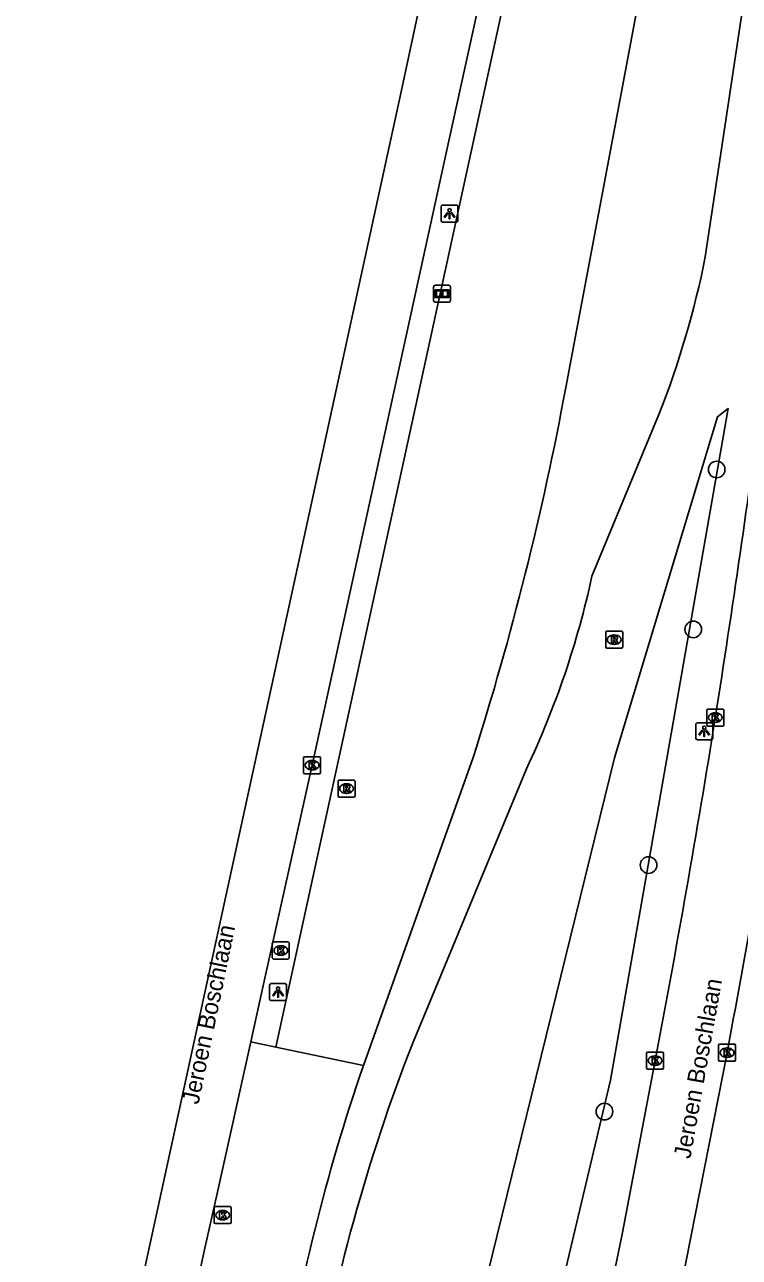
# Model space of a CAD drawing. Extents: x 163010 to 163853, y 382793 to 383982.
# Drawn here: x 163134.3 to 163176.4, y 382934.2 to 383006.7 of the extents above; entities that cross this region are included whole.
import ezdxf

# ---------------------------------------------------------------- set-up
doc = ezdxf.new("R2010")
doc.units = 0
for name, color, linetype in [('IMGEO_Berm_groen', 7, 'Continuous'), ('IMGEO_Boom', 7, 'Continuous'), ('IMGEO_Informatiebord', 7, 'Continuous'), ('IMGEO_Kolk', 7, 'Continuous'), ('IMGEO_Lichtpunt', 7, 'Continuous'), ('IMGEO_Openbare_ruimte_label', 7, 'Continuous'), ('IMGEO_Rijbaan_lokaal_gesloten', 7, 'Continuous'), ('IMGEO_Rijbaan_regionaal_gesloten', 7, 'Continuous'), ('IMGEO_Rioolput', 7, 'Continuous')]:
    doc.layers.add(name, color=color, linetype=linetype)

msp = doc.modelspace()

# ---------------------------------------------------------------- linework, layer by layer
at = {"layer": 'IMGEO_Berm_groen'}
for points in [[(163167.335, 383030.022), (163149.123, 382946.557)], [(163174.387, 382993.005), (163175.441, 383000), (163179.814, 383029.04)], [(163173.756, 383028.282), (163172.571, 383019.306), (163168.939, 383000), (163166.178, 382985.326)], [(163160.593, 382909.986), (163168.816, 382944.6), (163175.739, 382984.091), (163175.109, 382983.61), (163169.045, 382963.559), (163155.533, 382908.637)], [(163167.716, 382974.235), (163171.658, 382983.735)], [(163160.728, 382963.579), (163154.271, 382945.466)], [(163157.194, 382946.851), (163163.863, 382962.916)], [(163147.641, 382946.871), (163149.123, 382946.557)], [(163149.123, 382946.557), (163154.271, 382945.466)]]:
    msp.add_lwpolyline(points, dxfattribs=at)
for centre, radius, start, end in [((163120.584, 383003.807), 54.876, 338.54483, 348.64731), ((162989.182, 383018.126), 180.009, 342.36061, 349.5012), ((163116.601, 382985.319), 52.303, 334.63795, 347.76479), ((163256.409, 382908.014), 106.546, 158.62275, 170.52914), ((163259.849, 382908.974), 111.707, 160.93273, 171.28168)]:
    msp.add_arc(centre, radius, start, end, dxfattribs=at)
at = {"layer": 'IMGEO_Boom'}
for centre in [(163175.056, 382980.509), (163173.679, 382971.111), (163171.048, 382957.253), (163168.454, 382942.76)]:
    msp.add_circle(centre, 0.489, dxfattribs=at)
at = {"layer": 'IMGEO_Informatiebord'}
for p, q in [((163158.402, 382990.443), (163158.402, 382991.243)), ((163158.402, 382991.243), (163158.402, 382990.443)), ((163158.502, 382991.343), (163159.292, 382991.343)), ((163159.292, 382991.343), (163158.502, 382991.343)), ((163159.392, 382991.243), (163159.392, 382990.443)), ((163159.392, 382990.443), (163159.392, 382991.243)), ((163159.292, 382990.343), (163158.502, 382990.343)), ((163158.502, 382990.343), (163159.292, 382990.343))]:
    msp.add_line(p, q, dxfattribs=at)
for points in [[(163158.503, 382991.075), (163159.291, 382991.075), (163159.291, 382990.611), (163158.503, 382990.611), (163158.503, 382991.075)], [(163158.568, 382991.01), (163158.568, 382990.676), (163158.843, 382990.676), (163158.844, 382990.889), (163158.948, 382990.89), (163158.949, 382990.676), (163159.226, 382990.676), (163159.226, 382991.01), (163158.95, 382991.01), (163158.95, 382990.93), (163158.844, 382990.93), (163158.844, 382991.01), (163158.568, 382991.01)]]:
    msp.add_lwpolyline(points, dxfattribs=at)
for centre, start, end in [((163158.502, 382991.243), 90, 180), ((163158.502, 382991.243), 90, 180), ((163159.292, 382991.243), 0, 90), ((163159.292, 382991.243), 360, 90), ((163158.502, 382990.443), 180, 270), ((163158.502, 382990.443), 180, 270), ((163159.292, 382990.443), 270, 0), ((163159.292, 382990.443), 270, 0)]:
    msp.add_arc(centre, 0.1, start, end, dxfattribs=at)
at = {"layer": 'IMGEO_Kolk'}
for p, q in [((163174.474, 382965.499), (163174.474, 382966.351)), ((163174.549, 382966.425), (163175.401, 382966.425)), ((163174.962, 382966.205), (163174.987, 382966.205)), ((163175.475, 382966.351), (163175.475, 382965.499)), ((163175.401, 382965.425), (163174.549, 382965.425)), ((163174.985, 382965.645), (163174.96, 382965.645)), ((163150.753, 382962.698), (163150.753, 382963.55)), ((163150.828, 382963.624), (163151.68, 382963.624)), ((163151.241, 382963.404), (163151.266, 382963.404)), ((163151.754, 382963.55), (163151.754, 382962.698)), ((163151.68, 382962.624), (163150.828, 382962.624)), ((163151.264, 382962.844), (163151.239, 382962.844)), ((163148.913, 382951.806), (163148.913, 382952.658)), ((163148.988, 382952.732), (163149.84, 382952.732)), ((163149.401, 382952.512), (163149.426, 382952.512)), ((163149.914, 382952.658), (163149.914, 382951.806)), ((163149.84, 382951.732), (163148.988, 382951.732)), ((163149.424, 382951.952), (163149.399, 382951.952)), ((163175.168, 382945.798), (163175.168, 382946.65)), ((163175.243, 382946.724), (163176.095, 382946.724)), ((163175.656, 382946.504), (163175.681, 382946.504)), ((163176.169, 382946.65), (163176.169, 382945.798)), ((163170.93, 382945.331), (163170.93, 382946.183)), ((163171.005, 382946.257), (163171.857, 382946.257)), ((163171.418, 382946.037), (163171.443, 382946.037)), ((163171.931, 382946.183), (163171.931, 382945.331)), ((163176.095, 382945.724), (163175.243, 382945.724)), ((163175.679, 382945.944), (163175.654, 382945.944)), ((163171.857, 382945.257), (163171.005, 382945.257)), ((163171.441, 382945.477), (163171.416, 382945.477)), ((163145.494, 382936.248), (163145.494, 382937.1)), ((163145.569, 382937.174), (163146.421, 382937.174)), ((163145.982, 382936.954), (163146.007, 382936.954)), ((163146.495, 382937.1), (163146.495, 382936.248)), ((163146.421, 382936.174), (163145.569, 382936.174)), ((163146.005, 382936.394), (163145.98, 382936.394))]:
    msp.add_line(p, q, dxfattribs=at)
for points in [[(163174.474, 382965.499), (163174.474, 382966.351)], [(163174.549, 382966.425), (163175.401, 382966.425)], [(163174.795, 382966.125), (163174.918, 382966.125), (163174.918, 382965.974), (163175.048, 382966.125), (163175.212, 382966.125), (163175.066, 382965.974), (163175.219, 382965.725), (163175.067, 382965.725), (163174.982, 382965.889), (163174.918, 382965.822), (163174.918, 382965.725), (163174.795, 382965.725), (163174.795, 382966.125)], [(163175.475, 382966.351), (163175.475, 382965.499)], [(163175.401, 382965.425), (163174.549, 382965.425)], [(163150.753, 382962.698), (163150.753, 382963.55)], [(163150.828, 382963.624), (163151.68, 382963.624)], [(163151.074, 382963.324), (163151.197, 382963.324), (163151.197, 382963.173), (163151.327, 382963.324), (163151.491, 382963.324), (163151.345, 382963.173), (163151.498, 382962.924), (163151.346, 382962.924), (163151.261, 382963.088), (163151.197, 382963.021), (163151.197, 382962.924), (163151.074, 382962.924), (163151.074, 382963.324)], [(163151.754, 382963.55), (163151.754, 382962.698)], [(163151.68, 382962.624), (163150.828, 382962.624)], [(163148.913, 382951.806), (163148.913, 382952.658)], [(163148.988, 382952.732), (163149.84, 382952.732)], [(163149.234, 382952.432), (163149.357, 382952.432), (163149.357, 382952.281), (163149.487, 382952.432), (163149.651, 382952.432), (163149.505, 382952.281), (163149.658, 382952.032), (163149.506, 382952.032), (163149.421, 382952.196), (163149.357, 382952.129), (163149.357, 382952.032), (163149.234, 382952.032), (163149.234, 382952.432)], [(163149.914, 382952.658), (163149.914, 382951.806)], [(163149.84, 382951.732), (163148.988, 382951.732)], [(163175.168, 382945.798), (163175.168, 382946.65)], [(163175.243, 382946.724), (163176.095, 382946.724)], [(163175.489, 382946.424), (163175.612, 382946.424), (163175.612, 382946.273), (163175.742, 382946.424), (163175.906, 382946.424), (163175.76, 382946.273), (163175.913, 382946.024), (163175.761, 382946.024), (163175.676, 382946.188), (163175.612, 382946.121), (163175.612, 382946.024), (163175.489, 382946.024), (163175.489, 382946.424)], [(163176.169, 382946.65), (163176.169, 382945.798)], [(163170.93, 382945.331), (163170.93, 382946.183)], [(163171.005, 382946.257), (163171.857, 382946.257)], [(163171.251, 382945.957), (163171.374, 382945.957), (163171.374, 382945.806), (163171.504, 382945.957), (163171.668, 382945.957), (163171.522, 382945.806), (163171.675, 382945.557), (163171.523, 382945.557), (163171.438, 382945.721), (163171.374, 382945.654), (163171.374, 382945.557), (163171.251, 382945.557), (163171.251, 382945.957)], [(163171.931, 382946.183), (163171.931, 382945.331)], [(163176.095, 382945.724), (163175.243, 382945.724)], [(163171.857, 382945.257), (163171.005, 382945.257)], [(163145.494, 382936.248), (163145.494, 382937.1)], [(163145.569, 382937.174), (163146.421, 382937.174)], [(163146.495, 382937.1), (163146.495, 382936.248)], [(163146.421, 382936.174), (163145.569, 382936.174)], [(163145.815, 382936.874), (163145.938, 382936.874), (163145.938, 382936.723), (163146.068, 382936.874), (163146.232, 382936.874), (163146.086, 382936.723), (163146.239, 382936.474), (163146.087, 382936.474), (163146.002, 382936.638), (163145.938, 382936.571), (163145.938, 382936.474), (163145.815, 382936.474), (163145.815, 382936.874)]]:
    msp.add_lwpolyline(points, dxfattribs=at)
for centre, start, end in [((163174.551, 382966.349), 91.55205, 178.44795), ((163174.551, 382966.349), 91.55205, 178.44795), ((163175.399, 382966.349), 1.55205, 88.44795), ((163175.399, 382966.349), 1.55205, 88.44795), ((163174.551, 382965.501), 181.55205, 268.44795), ((163174.551, 382965.501), 181.55205, 268.44795), ((163175.399, 382965.501), 271.55205, 358.44795), ((163175.399, 382965.501), 271.55205, 358.44795), ((163150.83, 382963.548), 91.55205, 178.44795), ((163150.83, 382963.548), 91.55205, 178.44795), ((163151.678, 382963.548), 1.55205, 88.44795), ((163151.678, 382963.548), 1.55205, 88.44795), ((163150.83, 382962.7), 181.55205, 268.44795), ((163150.83, 382962.7), 181.55205, 268.44795), ((163151.678, 382962.7), 271.55205, 358.44795), ((163151.678, 382962.7), 271.55205, 358.44795), ((163148.99, 382952.656), 91.55205, 178.44795), ((163148.99, 382952.656), 91.55205, 178.44795), ((163149.838, 382952.656), 1.55205, 88.44795), ((163149.838, 382952.656), 1.55205, 88.44795), ((163148.99, 382951.808), 181.55205, 268.44795), ((163148.99, 382951.808), 181.55205, 268.44795), ((163149.838, 382951.808), 271.55205, 358.44795), ((163149.838, 382951.808), 271.55205, 358.44795), ((163175.245, 382946.648), 91.55205, 178.44795), ((163175.245, 382946.648), 91.55205, 178.44795), ((163176.093, 382946.648), 1.55205, 88.44795), ((163176.093, 382946.648), 1.55205, 88.44795), ((163171.007, 382946.181), 91.55205, 178.44795), ((163171.007, 382946.181), 91.55205, 178.44795), ((163171.855, 382946.181), 1.55205, 88.44795), ((163171.855, 382946.181), 1.55205, 88.44795), ((163175.245, 382945.8), 181.55205, 268.44795), ((163175.245, 382945.8), 181.55205, 268.44795), ((163176.093, 382945.8), 271.55205, 358.44795), ((163176.093, 382945.8), 271.55205, 358.44795), ((163171.007, 382945.333), 181.55205, 268.44795), ((163171.007, 382945.333), 181.55205, 268.44795), ((163171.855, 382945.333), 271.55205, 358.44795), ((163171.855, 382945.333), 271.55205, 358.44795), ((163145.571, 382937.098), 91.55205, 178.44795), ((163145.571, 382937.098), 91.55205, 178.44795), ((163146.419, 382937.098), 1.55205, 88.44795), ((163146.419, 382937.098), 1.55205, 88.44795), ((163145.571, 382936.25), 181.55205, 268.44795), ((163145.571, 382936.25), 181.55205, 268.44795), ((163146.419, 382936.25), 271.55205, 358.44795), ((163146.419, 382936.25), 271.55205, 358.44795)]:
    msp.add_arc(centre, 0.0765, start, end, dxfattribs=at)
for centre, major_axis, ratio, start_param, end_param in [((163174.961, 382965.925), (-0.387, 0.002), 0.722429, 4.712389, 7.853982), ((163174.986, 382965.925), (-0.39, 0.002), 0.717154, 1.570796, 4.712389), ((163151.24, 382963.124), (-0.387, 0.002), 0.722429, 4.712389, 7.853982), ((163151.265, 382963.124), (-0.39, 0.002), 0.717154, 1.570796, 4.712389), ((163149.4, 382952.232), (-0.387, 0.002), 0.722429, 4.712389, 7.853982), ((163149.425, 382952.232), (-0.39, 0.002), 0.717154, 1.570796, 4.712389), ((163175.655, 382946.224), (-0.387, 0.002), 0.722429, 4.712389, 7.853982), ((163175.68, 382946.224), (-0.39, 0.002), 0.717154, 1.570796, 4.712389), ((163171.417, 382945.757), (-0.387, 0.002), 0.722429, 4.712389, 7.853982), ((163171.442, 382945.757), (-0.39, 0.002), 0.717154, 1.570796, 4.712389), ((163145.981, 382936.674), (-0.387, 0.002), 0.722429, 4.712389, 7.853982), ((163146.006, 382936.674), (-0.39, 0.002), 0.717154, 1.570796, 4.712389)]:
    msp.add_ellipse(centre, major_axis=major_axis, ratio=ratio, start_param=start_param, end_param=end_param, dxfattribs=at)
at = {"layer": 'IMGEO_Lichtpunt'}
for p, q in [((163158.84, 382995.954), (163158.84, 382995.147)), ((163158.84, 382995.954), (163158.84, 382995.147)), ((163159.742, 382996.049), (163158.934, 382996.049)), ((163159.742, 382996.049), (163158.934, 382996.049)), ((163159.836, 382995.147), (163159.836, 382995.954)), ((163159.836, 382995.147), (163159.836, 382995.954)), ((163158.934, 382995.053), (163159.742, 382995.053)), ((163158.934, 382995.053), (163159.742, 382995.053)), ((163173.824, 382965.526), (163173.824, 382964.719)), ((163173.824, 382965.526), (163173.824, 382964.719)), ((163174.726, 382965.621), (163173.918, 382965.621)), ((163174.726, 382965.621), (163173.918, 382965.621)), ((163174.82, 382964.719), (163174.82, 382965.526)), ((163174.82, 382964.719), (163174.82, 382965.526)), ((163173.918, 382964.625), (163174.726, 382964.625)), ((163173.918, 382964.625), (163174.726, 382964.625)), ((163148.754, 382950.191), (163148.754, 382949.384)), ((163148.754, 382950.191), (163148.754, 382949.384)), ((163149.656, 382950.286), (163148.848, 382950.286)), ((163149.656, 382950.286), (163148.848, 382950.286)), ((163149.75, 382949.384), (163149.75, 382950.191)), ((163149.75, 382949.384), (163149.75, 382950.191)), ((163148.848, 382949.29), (163149.656, 382949.29)), ((163148.848, 382949.29), (163149.656, 382949.29))]:
    msp.add_line(p, q, dxfattribs=at)
for points in [[(163159.214, 382995.618), (163159.253, 382995.59), (163159.065, 382995.328), (163159.027, 382995.355), (163159.214, 382995.618)], [(163159.426, 382995.59), (163159.464, 382995.617), (163159.651, 382995.355), (163159.612, 382995.327), (163159.426, 382995.59)], [(163159.316, 382995.57), (163159.363, 382995.57), (163159.363, 382995.248), (163159.316, 382995.248), (163159.316, 382995.57)], [(163174.198, 382965.19), (163174.237, 382965.162), (163174.049, 382964.9), (163174.011, 382964.927), (163174.198, 382965.19)], [(163174.41, 382965.162), (163174.448, 382965.189), (163174.635, 382964.927), (163174.596, 382964.899), (163174.41, 382965.162)], [(163174.3, 382965.142), (163174.347, 382965.142), (163174.347, 382964.82), (163174.3, 382964.82), (163174.3, 382965.142)], [(163149.128, 382949.855), (163149.167, 382949.827), (163148.979, 382949.565), (163148.941, 382949.592), (163149.128, 382949.855)], [(163149.23, 382949.807), (163149.277, 382949.807), (163149.277, 382949.485), (163149.23, 382949.485), (163149.23, 382949.807)], [(163149.34, 382949.827), (163149.378, 382949.854), (163149.565, 382949.592), (163149.526, 382949.564), (163149.34, 382949.827)]]:
    msp.add_lwpolyline(points, dxfattribs=at)
for centre in [(163159.339, 382995.752), (163174.323, 382965.324), (163149.253, 382949.989)]:
    msp.add_circle(centre, 0.0994, dxfattribs=at)
for centre, start, end in [((163158.934, 382995.954), 90, 180), ((163158.934, 382995.954), 90, 180), ((163159.742, 382995.954), 0, 90), ((163159.742, 382995.954), 0, 90), ((163158.934, 382995.147), 180, 270), ((163158.934, 382995.147), 180, 270), ((163159.742, 382995.147), 270, 0), ((163159.742, 382995.147), 270, 360), ((163173.918, 382965.526), 90, 180), ((163173.918, 382965.526), 90, 180), ((163174.726, 382965.526), 0, 90), ((163174.726, 382965.526), 0, 90), ((163173.918, 382964.719), 180, 270), ((163173.918, 382964.719), 180, 270), ((163174.726, 382964.719), 270, 0), ((163174.726, 382964.719), 270, 360), ((163148.848, 382950.191), 90, 180), ((163148.848, 382950.191), 90, 180), ((163149.656, 382950.191), 0, 90), ((163149.656, 382950.191), 0, 90), ((163148.848, 382949.384), 180, 270), ((163148.848, 382949.384), 180, 270), ((163149.656, 382949.384), 270, 0), ((163149.656, 382949.384), 270, 360)]:
    msp.add_arc(centre, 0.0946, start, end, dxfattribs=at)
at = {"layer": 'IMGEO_Rijbaan_lokaal_gesloten'}
for points in [[(163171.432, 382945.756), (163169.511, 382935.663), (163167.659, 382926.597), (163165.762, 382916.593), (163164.894, 382914.338)], [(163175.667, 382946.223), (163171.652, 382925.833), (163168.024, 382907.139), (163167.356, 382903.331)]]:
    msp.add_lwpolyline(points, dxfattribs=at)
for centre, radius, start, end in [((162455.482, 383079.718), 728.437, 351.012697, 352.545845), ((162508.439, 383071.66), 678.917, 349.352787, 351.15287), ((162512.827, 383071.879), 670.572, 349.159112, 350.908885)]:
    msp.add_arc(centre, radius, start, end, dxfattribs=at)
at = {"layer": 'IMGEO_Rijbaan_regionaal_gesloten'}
for points in [[(163134.341, 382901.12), (163135.144, 382904.805), (163156.456, 383002.541), (163162.922, 383032.704)], [(163165.798, 383029.872), (163164.489, 383023.986), (163162.32, 383014.193), (163161.179, 383008.396), (163159.341, 383000), (163155.385, 382981.922), (163151.253, 382963.125), (163149.141, 382953.609), (163148.39, 382950.256), (163147.641, 382946.871)], [(163140.079, 382906.96), (163140.138, 382908.065), (163140.226, 382910.725), (163140.274, 382911.241), (163140.412, 382912.235), (163140.715, 382915.243), (163141.078, 382917.216), (163142.2, 382922.274), (163142.887, 382925.33), (163144.938, 382934.729), (163145.667, 382937.954), (163147.641, 382946.871)]]:
    msp.add_lwpolyline(points, dxfattribs=at)
at = {"layer": 'IMGEO_Rioolput'}
for p, q in [((163168.601, 382971.006), (163169.453, 382971.006)), ((163168.526, 382970.08), (163168.526, 382970.932)), ((163169.037, 382970.226), (163169.012, 382970.226)), ((163169.014, 382970.786), (163169.039, 382970.786)), ((163169.527, 382970.932), (163169.527, 382970.08)), ((163169.453, 382970.006), (163168.601, 382970.006)), ((163152.853, 382962.251), (163153.705, 382962.251)), ((163152.778, 382961.325), (163152.778, 382962.177)), ((163153.266, 382962.031), (163153.291, 382962.031)), ((163153.779, 382962.177), (163153.779, 382961.325)), ((163153.705, 382961.251), (163152.853, 382961.251)), ((163153.289, 382961.471), (163153.264, 382961.471))]:
    msp.add_line(p, q, dxfattribs=at)
for points in [[(163168.601, 382971.006), (163169.453, 382971.006)], [(163168.526, 382970.08), (163168.526, 382970.932)], [(163169.115, 382970.704), (163168.863, 382970.706), (163168.863, 382970.306)], [(163168.863, 382970.306), (163168.987, 382970.306), (163168.987, 382970.468), (163168.998, 382970.468)], [(163169.041, 382970.625), (163168.987, 382970.625), (163168.987, 382970.544)], [(163168.987, 382970.544), (163169.039, 382970.544)], [(163169.045, 382970.439), (163169.116, 382970.306), (163169.256, 382970.306), (163169.191, 382970.432)], [(163169.527, 382970.932), (163169.527, 382970.08)], [(163169.453, 382970.006), (163168.601, 382970.006)], [(163152.853, 382962.251), (163153.705, 382962.251)], [(163152.778, 382961.325), (163152.778, 382962.177)], [(163153.367, 382961.949), (163153.115, 382961.951), (163153.115, 382961.551)], [(163153.115, 382961.551), (163153.239, 382961.551), (163153.239, 382961.713), (163153.25, 382961.713)], [(163153.293, 382961.87), (163153.239, 382961.87), (163153.239, 382961.789)], [(163153.239, 382961.789), (163153.291, 382961.789)], [(163153.297, 382961.684), (163153.368, 382961.551), (163153.508, 382961.551), (163153.443, 382961.677)], [(163153.779, 382962.177), (163153.779, 382961.325)], [(163153.705, 382961.251), (163152.853, 382961.251)]]:
    msp.add_lwpolyline(points, dxfattribs=at)
for centre, radius, start, end in [((163168.603, 382970.93), 0.0765, 91.55205, 178.44795), ((163168.603, 382970.93), 0.0765, 91.55205, 178.44795), ((163169.451, 382970.93), 0.0765, 1.55205, 88.44795), ((163169.451, 382970.93), 0.0765, 1.55205, 88.44795), ((163168.997, 382970.415), 0.0533, 26.02933, 88.69889), ((163169.023, 382970.733), 0.19, 274.7715, 282.96867), ((163169.047, 382970.529), 0.0964, 77.00612, 93.18647), ((163169.061, 382970.586), 0.0378, 276.66336, 79.67722), ((163169.114, 382970.594), 0.109, 350.36119, 89.41601), ((163169.112, 382970.594), 0.112, 277.58423, 350.98172), ((163169.096, 382970.379), 0.108, 29.51342, 73.79051), ((163168.603, 382970.082), 0.0765, 181.55205, 268.44795), ((163168.603, 382970.082), 0.0765, 181.55205, 268.44795), ((163169.451, 382970.082), 0.0765, 271.55205, 358.44795), ((163169.451, 382970.082), 0.0765, 271.55205, 358.44795), ((163152.855, 382962.175), 0.0765, 91.55205, 178.44795), ((163152.855, 382962.175), 0.0765, 91.55205, 178.44795), ((163153.703, 382962.175), 0.0765, 1.55205, 88.44795), ((163153.703, 382962.175), 0.0765, 1.55205, 88.44795), ((163153.249, 382961.66), 0.0533, 26.02933, 88.69889), ((163153.275, 382961.978), 0.19, 274.7715, 282.96867), ((163153.299, 382961.774), 0.0964, 77.00612, 93.18647), ((163153.313, 382961.831), 0.0378, 276.66336, 79.67722), ((163153.366, 382961.839), 0.109, 350.36119, 89.41601), ((163153.364, 382961.839), 0.112, 277.58423, 350.98172), ((163153.348, 382961.624), 0.108, 29.51342, 73.79051), ((163152.855, 382961.327), 0.0765, 181.55205, 268.44795), ((163152.855, 382961.327), 0.0765, 181.55205, 268.44795), ((163153.703, 382961.327), 0.0765, 271.55205, 358.44795), ((163153.703, 382961.327), 0.0765, 271.55205, 358.44795)]:
    msp.add_arc(centre, radius, start, end, dxfattribs=at)
for centre, major_axis, ratio, start_param, end_param in [((163169.013, 382970.506), (-0.387, 0.002), 0.722429, 4.712389, 7.853982), ((163169.038, 382970.506), (-0.39, 0.002), 0.717154, 1.570796, 4.712389), ((163153.265, 382961.751), (-0.387, 0.002), 0.722429, 4.712389, 7.853982), ((163153.29, 382961.751), (-0.39, 0.002), 0.717154, 1.570796, 4.712389)]:
    msp.add_ellipse(centre, major_axis=major_axis, ratio=ratio, start_param=start_param, end_param=end_param, dxfattribs=at)

# ---------------------------------------------------------------- texts
at = {"layer": 'IMGEO_Openbare_ruimte_label'}
for rotation, p in [(78.3416, (163144.569, 382943.144)), (79.92567, (163173.505, 382939.949))]:
    msp.add_text('Jeroen Boschlaan', height=1, rotation=rotation, dxfattribs=at).set_placement(p)

doc.saveas('drawing.dxf')
